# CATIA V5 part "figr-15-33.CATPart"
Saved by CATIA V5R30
Part number: Part1
Bounding box of the stored display mesh (mm): x -40.264 to 42.014, y -25.445 to 25.445, z -51 to 0.75
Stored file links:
  D:\PROJECTS\CATIA V56R 2020\Resources\Parts File\c15_catia_v5_6r2020_prt\figr-15-33.CATPart
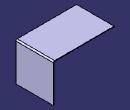
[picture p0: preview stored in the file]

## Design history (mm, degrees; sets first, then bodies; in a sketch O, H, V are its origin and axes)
SheetMetalParameters1: Thickness 0.75, BendRadius 1, KFactor 0.356492 {= log(min(100,max(20*SheetMetalParameters1.BendRadius,SheetMetalParameters1.Thickness)/SheetMetalParameters1.Thickness))/log(100)/2}, ReliefRadialLength 1, ReliefAxialLength 2, MinimumBendRadius 0
Body1 (main body)
  Sketch1 on xy-plane, origin (0, 0, 0), H (1, 0, 0), V (0, 1, 0)
    line L1 (-40.2643, 25.445) -> (40.2643, 25.445)
    line L2 (40.2643, 25.445) -> (40.2643, -25.445)
    line L3 (40.2643, -25.445) -> (-40.2643, -25.445)
    line L4 (-40.2643, -25.445) -> (-40.2643, 25.445)
    horizontal: L1 H, L3 H
    vertical: L2 V, L4 V
    symmetry: L1 L3 H, L4 L2 V
  Wall1: Thickness 0.75, Profile Sketch1
  Flange1: Angle 90, Length 50, Radius 1, KFacteur 0.356492 {= log(min(100,max(20*Flange1.Radius,SheetMetalParameters1.Thickness)/SheetMetalParameters1.Thickness))/log(100)/2}, Guide edge [face of Wall1 | face of Wall1]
